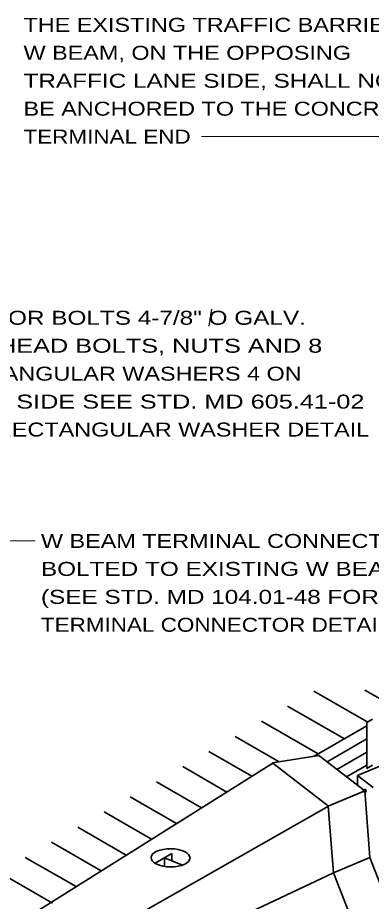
# Model space of a CAD drawing. Extents: x 12.4 to 19.52, y 6.05 to 15.92.
# Drawn here: x 15.119 to 16.636, y 12.12 to 15.915 of the extents above; entities that cross this region are included whole.
import ezdxf

# ---------------------------------------------------------------- set-up
doc = ezdxf.new("R2010")
doc.units = 0
doc.header["$LTSCALE"] = 0.024
doc.header["$PDMODE"] = 32
doc.header["$PDSIZE"] = 0.012
for name, color, linetype, lineweight in [('1', 7, 'Continuous', 35), ('10', 7, 'Continuous', 13), ('12', 7, 'Continuous', 53)]:
    doc.layers.add(name, color=color, linetype=linetype, lineweight=lineweight)

msp = doc.modelspace()

# ---------------------------------------------------------------- linework, layer by layer
at = {"layer": '1'}
for p, q in [((16.5757, 12.6615), (17.8774, 13.2067)), ((16.6203, 12.8903), (16.3892, 13.0237)), ((16.6075, 13.0276), (16.7451, 12.9482)), ((16.5201, 12.8183), (16.2767, 12.9588)), ((16.4076, 12.7533), (16.1642, 12.8939)), ((16.3908, 12.7437), (16.6169, 12.8741)), ((16.6169, 12.8883), (16.6414, 12.9024)), ((16.6169, 12.8883), (16.6169, 12.6905)), ((16.2401, 12.7202), (16.0518, 12.8289)), ((16.4461, 12.7191), (16.6169, 12.8177)), ((16.1232, 12.6578), (15.9393, 12.764)), ((16.4881, 12.6869), (16.6169, 12.7613)), ((16.2127, 12.714), (15.062, 11.9906)), ((16.2124, 12.7156), (16.4107, 12.7465)), ((16.4515, 12.5297), (16.2127, 12.714)), ((16.6073, 12.5948), (16.4107, 12.7465)), ((16.0155, 12.59), (15.8268, 12.699)), ((16.5299, 12.6545), (16.6169, 12.7047)), ((16.6169, 12.6905), (16.6414, 12.7046)), ((16.5757, 12.6615), (16.6431, 12.6098)), ((16.5757, 12.6615), (16.5757, 12.6201)), ((15.9078, 12.5223), (15.7143, 12.6341)), ((15.8001, 12.4546), (15.6018, 12.5691)), ((16.6073, 12.5948), (16.4509, 12.5293)), ((16.4515, 12.5297), (15.2822, 11.8634)), ((16.4732, 12.2435), (16.4509, 12.5293)), ((15.6924, 12.3869), (15.4893, 12.5042)), ((15.5847, 12.3191), (15.3768, 12.4392)), ((15.477, 12.2514), (15.2643, 12.3743)), ((15.3693, 12.1838), (15.1518, 12.3093)), ((15.7082, 12.2838), (15.7801, 12.3254)), ((15.749, 12.3066), (15.8266, 12.2754)), ((15.749, 12.3066), (15.749, 12.2707)), ((15.7801, 12.3254), (15.7801, 12.2943)), ((16.4732, 12.2435), (16.6297, 12.309)), ((15.2677, 12.1125), (15.0393, 12.2444))]:
    msp.add_line(p, q, dxfattribs=at)
for points in [[(16.7079, 12.1071), (16.6297, 12.309), (16.6073, 12.5948)], [(16.5514, 12.0416), (16.4732, 12.2435), (15.2822, 11.6797)]]:
    msp.add_lwpolyline(points, dxfattribs=at)
msp.add_ellipse((15.7746, 12.3073), major_axis=(0.08358, -0.00086), ratio=0.468129, dxfattribs=at)
msp.add_point((16.6073, 12.5948), dxfattribs=at)
at = {"layer": '10'}
for p, q in [((15.9072, 15.4046), (16.7513, 15.4046)), ((15.1938, 13.6681), (14.5018, 13.6681))]:
    msp.add_line(p, q, dxfattribs=at)
at = {"layer": '10', "lineweight": 25}
msp.add_line((15.9402, 14.5902), (15.9511, 14.6638), dxfattribs=at)

# ---------------------------------------------------------------- texts
at = {"layer": '12'}
for s, width, p in [('THE EXISTING TRAFFIC BARRIER', 1.25, (15.1442, 15.8546)), ('W BEAM, ON THE OPPOSING', 1.25, (15.1442, 15.7346)), ('TRAFFIC LANE SIDE, SHALL NOT', 1.3, (15.1442, 15.6146)), ('BE ANCHORED TO THE CONCRETE', 1.25, (15.1442, 15.4946)), ('TERMINAL END', 1.2, (15.1442, 15.3746)), ('ANCHOR BOLTS 4-7/8" O GALV.', 1.3, (14.7821, 14.5966)), ('HEX HEAD BOLTS, NUTS AND 8', 1.35, (14.7821, 14.4766)), ('RECTANGULAR WASHERS 4 ON', 1.25, (14.7821, 14.3566)), ('EACH SIDE SEE STD. MD 605.41-02', 1.35, (14.7821, 14.2366)), ('FOR RECTANGULAR WASHER DETAIL', 1.25, (14.7821, 14.1166)), ('W BEAM TERMINAL CONNECTOR SPLICE', 1.25, (15.2188, 13.6381)), ('BOLTED TO EXISTING W BEAM', 1.3, (15.2188, 13.5181)), ('(SEE STD. MD 104.01-48 FOR', 1.3, (15.2188, 13.3981)), ('TERMINAL CONNECTOR DETAILS)', 1.2, (15.2188, 13.2781))]:
    msp.add_text(s, height=0.06, dxfattribs=dict(at, width=width)).set_placement(p)

doc.saveas('drawing.dxf')
